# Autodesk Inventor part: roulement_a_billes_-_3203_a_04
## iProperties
Shininess: 64.0
Length Units: 11269
Angle Units: 11279
Time Units: 11290
Mass Units: 11283
Length Display Precision: 3
Angle Display Precision: 2
Compacted: True
Part Number: roulement_a_billes_-_3203_a_04
Document SubType Name: Modeling
Created: 2005-02
Material: Par défaut
Designer: LEGERET Philippe
Density: 0.0
Volumn: 0.0
Area: 0.0
PropertySet Name: Model Information
Control State: 0
Master: False
Checked Out: False
Author: LEGERET Philippe
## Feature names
1. Base1
